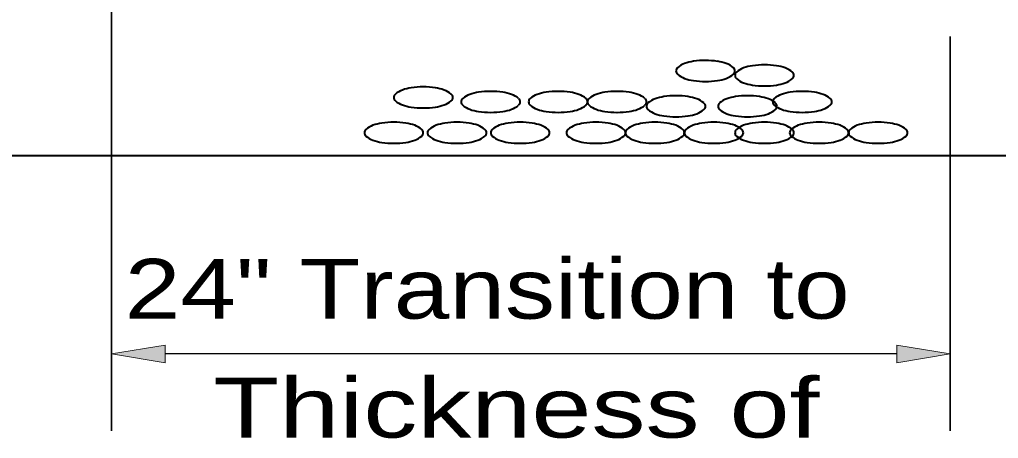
# Model space of a CAD drawing. Extents: x 36.4 to 71.7, y 0.5 to 22.5.
# Drawn here: x 55.644 to 57.934, y 7.945 to 8.925 of the extents above; entities that cross this region are included whole.
import ezdxf

# ---------------------------------------------------------------- set-up
doc = ezdxf.new("R2010")
doc.units = 0
doc.header["$LTSCALE"] = 0.056
for name, color, linetype, lineweight in [('1', 7, 'Continuous', 40), ('3', 7, 'Continuous', 13), ('6', 7, 'Continuous', 13)]:
    doc.layers.add(name, color=color, linetype=linetype, lineweight=lineweight)

msp = doc.modelspace()

# ---------------------------------------------------------------- hatches: boundary and pattern name
at = {"layer": '1'}
for points in [[(55.984, 8.12142), (55.984, 8.163), (55.859, 8.14225), (55.859, 8.14225)], [(57.696, 8.12142), (57.696, 8.163), (57.821, 8.14225), (57.821, 8.14225)]]:
    msp.add_hatch(color=256, dxfattribs=at).paths.add_polyline_path(points)

# ---------------------------------------------------------------- linework, layer by layer
at = {"layer": '1', "lineweight": 35}
for p, q in [((55.859, 9.051), (55.859, 7.96225)), ((57.821, 8.88583), (57.821, 7.96225))]:
    msp.add_line(p, q, dxfattribs=at)
at = {"layer": '1'}
msp.add_line((53.98842, 8.60725), (58.57958, 8.60725), dxfattribs=at)
at = {"layer": '1', "lineweight": 25}
msp.add_line((57.696, 8.14225), (55.984, 8.14225), dxfattribs=at)
at = {"layer": '1', "lineweight": 13}
for points in [[(55.984, 8.12142), (55.984, 8.163), (55.859, 8.14225), (55.859, 8.14225)], [(57.696, 8.12142), (57.696, 8.163), (57.821, 8.14225), (57.821, 8.14225)]]:
    msp.add_lwpolyline(points, close=True, dxfattribs=at)
at = {"layer": '1'}
for centre, radius, start, end in [((57.21717, 8.77267), 0.05258, 109.55636, 130.6711), ((57.23617, 8.72025), 0.10836, 98.47139, 109.71022), ((57.24842, 8.637), 0.19248, 90.02264, 98.43766), ((57.24833, 8.63642), 0.19304, 81.57477, 89.98979), ((57.26058, 8.72067), 0.10795, 70.23479, 81.47362), ((57.2795, 8.77267), 0.05258, 49.32889, 70.44364), ((57.38633, 8.62667), 0.19248, 90.02264, 98.43766), ((57.38625, 8.62608), 0.19304, 81.57477, 89.98979), ((57.18958, 8.80492), 0.01021, 131.07972, 180.31117), ((57.1895, 8.80483), 0.01012, 179.922, 229.15345), ((57.21742, 8.837), 0.05269, 229.11499, 250.22974), ((57.27925, 8.837), 0.05269, 289.77026, 310.885), ((57.30708, 8.80483), 0.01025, 0.19847, 49.42992), ((57.30717, 8.80492), 0.01016, 310.3333, 359.56474), ((57.3275, 8.79458), 0.01021, 131.07972, 180.31117), ((57.32742, 8.7945), 0.01012, 179.922, 229.15345), ((57.35508, 8.76233), 0.05258, 109.55636, 130.6711), ((57.37408, 8.70992), 0.10836, 98.47139, 109.71022), ((57.3985, 8.70992), 0.10836, 70.28977, 81.5286), ((57.4175, 8.76233), 0.05258, 49.32889, 70.44364), ((57.44508, 8.79458), 0.01021, 359.68883, 48.92027), ((57.44517, 8.7945), 0.01012, 310.84655, 0.07799), ((57.23617, 8.88942), 0.10836, 250.28977, 261.5286), ((57.24783, 8.97267), 0.19243, 261.73096, 270.14599), ((57.24883, 8.97325), 0.193, 269.84207, 278.25709), ((57.26058, 8.889), 0.10795, 278.52638, 289.76521), ((57.35533, 8.82667), 0.05269, 229.11499, 250.22974), ((57.37408, 8.87908), 0.10836, 250.28977, 261.5286), ((57.38575, 8.96233), 0.19243, 261.73096, 270.14599), ((57.38675, 8.96292), 0.193, 269.84207, 278.25709), ((57.3985, 8.87908), 0.10836, 278.47139, 289.71023), ((57.41725, 8.82667), 0.05269, 289.77026, 310.885), ((56.52942, 8.74275), 0.01016, 130.3333, 179.56474), ((56.55733, 8.71067), 0.05269, 109.77026, 130.885), ((56.576, 8.65867), 0.10795, 98.52638, 109.76521), ((56.58825, 8.57442), 0.19304, 90.0102, 98.42523), ((56.58817, 8.575), 0.19248, 81.56233, 89.97736), ((56.60042, 8.65825), 0.10836, 70.28977, 81.5286), ((56.61917, 8.71067), 0.05269, 49.11499, 70.22974), ((56.64708, 8.74275), 0.01016, 0.43525, 49.6667), ((56.71492, 8.70033), 0.05269, 109.77026, 130.885), ((56.73367, 8.64792), 0.10836, 98.47139, 109.71022), ((56.74542, 8.56408), 0.193, 89.84207, 98.25709), ((56.74642, 8.56467), 0.19243, 81.73096, 90.14599), ((56.75808, 8.64792), 0.10836, 70.28977, 81.5286), ((56.77683, 8.70033), 0.05269, 49.11499, 70.22974), ((56.87258, 8.70033), 0.05269, 109.77026, 130.885), ((56.89133, 8.64792), 0.10836, 98.47139, 109.71022), ((56.903, 8.56467), 0.19243, 89.85401, 98.26903), ((56.904, 8.56408), 0.193, 81.7429, 90.15793), ((56.91575, 8.64833), 0.10795, 70.23479, 81.47362), ((56.93442, 8.70033), 0.05269, 49.11499, 70.22974), ((57.0105, 8.70033), 0.05269, 109.77026, 130.885), ((57.02925, 8.64792), 0.10836, 98.47139, 109.71022), ((57.04092, 8.56467), 0.19243, 89.85401, 98.26903), ((57.04192, 8.56408), 0.193, 81.7429, 90.15793), ((57.05367, 8.64792), 0.10836, 70.28977, 81.5286), ((57.07242, 8.70033), 0.05269, 49.11499, 70.22974), ((57.444, 8.70033), 0.05269, 109.77026, 130.885), ((57.46275, 8.64792), 0.10836, 98.47139, 109.71022), ((57.4745, 8.56408), 0.193, 89.84207, 98.25709), ((57.4755, 8.56467), 0.19243, 81.73096, 90.14599), ((57.48717, 8.64792), 0.10836, 70.28977, 81.5286), ((57.50592, 8.70033), 0.05269, 49.11499, 70.22974), ((56.5295, 8.74283), 0.01025, 180.19847, 229.42992), ((56.55708, 8.775), 0.05258, 229.32889, 250.44364), ((56.61942, 8.775), 0.05258, 289.55636, 310.6711), ((56.647, 8.74283), 0.01025, 310.57008, 359.80152), ((56.68708, 8.73242), 0.01021, 179.68883, 228.92027), ((56.687, 8.7325), 0.01012, 130.84655, 180.07799), ((56.80475, 8.7325), 0.01012, 359.922, 49.15345), ((56.80467, 8.73242), 0.01021, 311.07972, 0.31117), ((56.84475, 8.73242), 0.01021, 179.68883, 228.92027), ((56.84467, 8.7325), 0.01012, 130.84655, 180.07799), ((56.96233, 8.73242), 0.01016, 0.43525, 49.6667), ((56.96225, 8.7325), 0.01025, 310.57008, 359.80152), ((56.98258, 8.7325), 0.01012, 130.84655, 180.07799), ((56.98267, 8.73242), 0.01021, 179.68883, 228.92027), ((57.10033, 8.7325), 0.01012, 359.922, 49.15345), ((57.10025, 8.73242), 0.01021, 311.07972, 0.31117), ((57.1205, 8.72217), 0.01012, 130.84655, 180.07799), ((57.14842, 8.69), 0.05269, 109.77026, 130.885), ((57.16717, 8.63758), 0.10836, 98.47139, 109.71022), ((57.17892, 8.55375), 0.193, 89.84207, 98.25709), ((57.17992, 8.55433), 0.19243, 81.73096, 90.14599), ((57.19158, 8.63758), 0.10836, 70.28977, 81.5286), ((57.21033, 8.69), 0.05269, 49.11499, 70.22974), ((57.23825, 8.72217), 0.01012, 359.922, 49.15345), ((57.288, 8.72217), 0.01012, 130.84655, 180.07799), ((57.31592, 8.69), 0.05269, 109.77026, 130.885), ((57.33467, 8.63758), 0.10836, 98.47139, 109.71022), ((57.34642, 8.55375), 0.193, 89.84207, 98.25709), ((57.34742, 8.55433), 0.19243, 81.73096, 90.14599), ((57.35908, 8.63758), 0.10836, 70.28977, 81.5286), ((57.37783, 8.69), 0.05269, 49.11499, 70.22974), ((57.41608, 8.7325), 0.01012, 130.84655, 180.07799), ((57.41617, 8.73242), 0.01021, 179.68883, 228.92027), ((57.40575, 8.72217), 0.01012, 359.922, 49.15345), ((57.53383, 8.7325), 0.01012, 359.922, 49.15345), ((57.53375, 8.73242), 0.01021, 311.07972, 0.31117), ((56.576, 8.827), 0.10795, 250.23479, 261.47362), ((56.58825, 8.91125), 0.19304, 261.57477, 269.98979), ((56.58817, 8.91067), 0.19248, 270.02264, 278.43766), ((56.60042, 8.82742), 0.10836, 278.47139, 289.71023), ((56.71467, 8.76467), 0.05258, 229.32889, 250.44364), ((56.73367, 8.81708), 0.10836, 250.28977, 261.5286), ((56.74592, 8.90092), 0.19304, 261.57477, 269.98979), ((56.74583, 8.90033), 0.19248, 270.02264, 278.43766), ((56.75808, 8.81708), 0.10836, 278.47139, 289.71023), ((56.77708, 8.76467), 0.05258, 289.55636, 310.6711), ((56.87233, 8.76467), 0.05258, 229.32889, 250.44364), ((56.89133, 8.81708), 0.10836, 250.28977, 261.5286), ((56.90358, 8.90033), 0.19248, 261.56233, 269.97736), ((56.9035, 8.90092), 0.19304, 270.0102, 278.42523), ((56.91575, 8.81667), 0.10795, 278.52638, 289.76521), ((56.93467, 8.76467), 0.05258, 289.55636, 310.6711), ((57.01025, 8.76467), 0.05258, 229.32889, 250.44364), ((57.02925, 8.81708), 0.10836, 250.28977, 261.5286), ((57.0415, 8.90033), 0.19248, 261.56233, 269.97736), ((57.04142, 8.90092), 0.19304, 270.0102, 278.42523), ((57.05367, 8.81708), 0.10836, 278.47139, 289.71023), ((57.07267, 8.76467), 0.05258, 289.55636, 310.6711), ((57.12058, 8.72208), 0.01021, 179.68883, 228.92027), ((57.14817, 8.75433), 0.05258, 229.32889, 250.44364), ((57.16717, 8.80675), 0.10836, 250.28977, 261.5286), ((57.19158, 8.80675), 0.10836, 278.47139, 289.71023), ((57.21058, 8.75433), 0.05258, 289.55636, 310.6711), ((57.23817, 8.72208), 0.01021, 311.07972, 0.31117), ((57.28808, 8.72208), 0.01021, 179.68883, 228.92027), ((57.31567, 8.75433), 0.05258, 229.32889, 250.44364), ((57.33467, 8.80675), 0.10836, 250.28977, 261.5286), ((57.35908, 8.80675), 0.10836, 278.47139, 289.71023), ((57.37808, 8.75433), 0.05258, 289.55636, 310.6711), ((57.44375, 8.76467), 0.05258, 229.32889, 250.44364), ((57.40567, 8.72208), 0.01021, 311.07972, 0.31117), ((57.46275, 8.81708), 0.10836, 250.28977, 261.5286), ((57.475, 8.90092), 0.19304, 261.57477, 269.98979), ((57.47492, 8.90033), 0.19248, 270.02264, 278.43766), ((57.48717, 8.81708), 0.10836, 278.47139, 289.71023), ((57.50617, 8.76467), 0.05258, 289.55636, 310.6711), ((56.50658, 8.5755), 0.10826, 98.25297, 109.4918), ((56.51933, 8.49225), 0.19248, 90.02264, 98.43766), ((56.51925, 8.49167), 0.19304, 81.57477, 89.98979), ((56.532, 8.5755), 0.10826, 70.5082, 81.74703), ((56.65442, 8.57592), 0.10785, 98.30717, 109.546), ((56.66708, 8.49167), 0.19304, 90.0102, 98.42523), ((56.667, 8.49225), 0.19248, 81.56233, 89.97736), ((56.67975, 8.5755), 0.10826, 70.5082, 81.74703), ((56.80217, 8.5755), 0.10826, 98.25297, 109.4918), ((56.81492, 8.49225), 0.19248, 90.02264, 98.43766), ((56.81483, 8.49167), 0.19304, 81.57477, 89.98979), ((56.8275, 8.57592), 0.10785, 70.454, 81.69283), ((56.9795, 8.5755), 0.10826, 98.25297, 109.4918), ((56.99225, 8.49225), 0.19248, 90.02264, 98.43766), ((56.99217, 8.49167), 0.19304, 81.57477, 89.98979), ((57.00492, 8.5755), 0.10826, 70.5082, 81.74703), ((57.11742, 8.5755), 0.10826, 98.25297, 109.4918), ((57.13017, 8.49167), 0.19304, 90.0102, 98.42523), ((57.13008, 8.49225), 0.19248, 81.56233, 89.97736), ((57.17942, 8.89058), 0.19304, 261.57477, 269.98979), ((57.14283, 8.5755), 0.10826, 70.5082, 81.74703), ((57.17933, 8.89), 0.19248, 270.02264, 278.43766), ((57.25542, 8.57592), 0.10785, 98.30717, 109.546), ((57.26808, 8.49167), 0.19304, 90.0102, 98.42523), ((57.268, 8.49225), 0.19248, 81.56233, 89.97736), ((57.28075, 8.5755), 0.10826, 70.5082, 81.74703), ((57.34692, 8.89058), 0.19304, 261.57477, 269.98979), ((57.37358, 8.5755), 0.10826, 98.25297, 109.4918), ((57.34683, 8.89), 0.19248, 270.02264, 278.43766), ((57.38633, 8.49225), 0.19248, 90.02264, 98.43766), ((57.38625, 8.49167), 0.19304, 81.57477, 89.98979), ((57.399, 8.5755), 0.10826, 70.5082, 81.74703), ((57.50167, 8.5755), 0.10826, 98.25297, 109.4918), ((57.51442, 8.49225), 0.19248, 90.02264, 98.43766), ((57.51433, 8.49167), 0.19304, 81.57477, 89.98979), ((57.52708, 8.5755), 0.10826, 70.5082, 81.74703), ((57.63958, 8.5755), 0.10826, 98.25297, 109.4918), ((57.65233, 8.49167), 0.19304, 90.0102, 98.42523), ((57.65225, 8.49225), 0.19248, 81.56233, 89.97736), ((57.665, 8.5755), 0.10826, 70.5082, 81.74703), ((56.4605, 8.66008), 0.01021, 179.68883, 228.92027), ((56.46042, 8.66017), 0.01012, 130.84655, 180.07799), ((56.48833, 8.628), 0.05269, 109.77026, 130.885), ((56.55025, 8.628), 0.05269, 49.11499, 70.22974), ((56.57817, 8.66017), 0.01012, 359.922, 49.15345), ((56.57808, 8.66008), 0.01021, 311.07972, 0.31117), ((56.60833, 8.66017), 0.01025, 180.19847, 229.42992), ((56.60825, 8.66008), 0.01016, 130.3333, 179.56474), ((56.63617, 8.628), 0.05269, 109.77026, 130.885), ((56.698, 8.628), 0.05269, 49.11499, 70.22974), ((56.72592, 8.66017), 0.01012, 359.922, 49.15345), ((56.72583, 8.66008), 0.01021, 311.07972, 0.31117), ((56.75608, 8.66008), 0.01021, 179.68883, 228.92027), ((56.756, 8.66017), 0.01012, 130.84655, 180.07799), ((56.78392, 8.628), 0.05269, 109.77026, 130.885), ((56.84575, 8.628), 0.05269, 49.11499, 70.22974), ((56.87367, 8.66008), 0.01016, 0.43525, 49.6667), ((56.87358, 8.66017), 0.01025, 310.57008, 359.80152), ((56.93333, 8.66017), 0.01012, 130.84655, 180.07799), ((56.93342, 8.66008), 0.01021, 179.68883, 228.92027), ((56.96125, 8.628), 0.05269, 109.77026, 130.885), ((57.02317, 8.628), 0.05269, 49.11499, 70.22974), ((57.05108, 8.66017), 0.01012, 359.922, 49.15345), ((57.051, 8.66008), 0.01021, 311.07972, 0.31117), ((57.07133, 8.66008), 0.01021, 179.68883, 228.92027), ((57.07125, 8.66017), 0.01012, 130.84655, 180.07799), ((57.09917, 8.628), 0.05269, 109.77026, 130.885), ((57.16108, 8.628), 0.05269, 49.11499, 70.22974), ((57.189, 8.66017), 0.01012, 359.922, 49.15345), ((57.18892, 8.66008), 0.01021, 311.07972, 0.31117), ((57.20933, 8.66017), 0.01025, 180.19847, 229.42992), ((57.20925, 8.66008), 0.01016, 130.3333, 179.56474), ((57.23717, 8.628), 0.05269, 109.77026, 130.885), ((57.299, 8.628), 0.05269, 49.11499, 70.22974), ((57.3275, 8.66008), 0.01021, 179.68883, 228.92027), ((57.32742, 8.66017), 0.01012, 130.84655, 180.07799), ((57.35533, 8.628), 0.05269, 109.77026, 130.885), ((57.32692, 8.66017), 0.01012, 359.922, 49.15345), ((57.32683, 8.66008), 0.01021, 311.07972, 0.31117), ((57.41725, 8.628), 0.05269, 49.11499, 70.22974), ((57.45558, 8.66008), 0.01021, 179.68883, 228.92027), ((57.4555, 8.66017), 0.01012, 130.84655, 180.07799), ((57.48342, 8.628), 0.05269, 109.77026, 130.885), ((57.44517, 8.66017), 0.01012, 359.922, 49.15345), ((57.44508, 8.66008), 0.01021, 311.07972, 0.31117), ((57.54533, 8.628), 0.05269, 49.11499, 70.22974), ((57.57325, 8.66017), 0.01012, 359.922, 49.15345), ((57.57317, 8.66008), 0.01021, 311.07972, 0.31117), ((57.5935, 8.66008), 0.01021, 179.68883, 228.92027), ((57.59342, 8.66017), 0.01012, 130.84655, 180.07799), ((57.62133, 8.628), 0.05269, 109.77026, 130.885), ((57.68325, 8.628), 0.05269, 49.11499, 70.22974), ((57.71117, 8.66017), 0.01012, 359.922, 49.15345), ((57.71108, 8.66008), 0.01021, 311.07972, 0.31117), ((56.48808, 8.69233), 0.05258, 229.32889, 250.44364), ((56.50708, 8.74475), 0.10836, 250.28977, 261.5286), ((56.51933, 8.828), 0.19248, 261.56233, 269.97736), ((56.51925, 8.82858), 0.19304, 270.0102, 278.42523), ((56.5315, 8.74475), 0.10836, 278.47139, 289.71023), ((56.5505, 8.69233), 0.05258, 289.55636, 310.6711), ((56.63592, 8.69233), 0.05258, 229.32889, 250.44364), ((56.65483, 8.74433), 0.10795, 250.23479, 261.47362), ((56.66708, 8.82858), 0.19304, 261.57477, 269.98979), ((56.667, 8.828), 0.19248, 270.02264, 278.43766), ((56.67925, 8.74475), 0.10836, 278.47139, 289.71023), ((56.69825, 8.69233), 0.05258, 289.55636, 310.6711), ((56.78367, 8.69233), 0.05258, 229.32889, 250.44364), ((56.80267, 8.74475), 0.10836, 250.28977, 261.5286), ((56.81492, 8.828), 0.19248, 261.56233, 269.97736), ((56.81483, 8.82858), 0.19304, 270.0102, 278.42523), ((56.82708, 8.74433), 0.10795, 278.52638, 289.76521), ((56.846, 8.69233), 0.05258, 289.55636, 310.6711), ((56.961, 8.69233), 0.05258, 229.32889, 250.44364), ((56.98, 8.74475), 0.10836, 250.28977, 261.5286), ((56.99225, 8.828), 0.19248, 261.56233, 269.97736), ((56.99217, 8.82858), 0.19304, 270.0102, 278.42523), ((57.00442, 8.74475), 0.10836, 278.47139, 289.71023), ((57.02342, 8.69233), 0.05258, 289.55636, 310.6711), ((57.09892, 8.69233), 0.05258, 229.32889, 250.44364), ((57.11792, 8.74475), 0.10836, 250.28977, 261.5286), ((57.13017, 8.82858), 0.19304, 261.57477, 269.98979), ((57.13008, 8.828), 0.19248, 270.02264, 278.43766), ((57.14233, 8.74475), 0.10836, 278.47139, 289.71023), ((57.16133, 8.69233), 0.05258, 289.55636, 310.6711), ((57.23692, 8.69233), 0.05258, 229.32889, 250.44364), ((57.25583, 8.74433), 0.10795, 250.23479, 261.47362), ((57.26808, 8.82858), 0.19304, 261.57477, 269.98979), ((57.268, 8.828), 0.19248, 270.02264, 278.43766), ((57.28025, 8.74475), 0.10836, 278.47139, 289.71023), ((57.29925, 8.69233), 0.05258, 289.55636, 310.6711), ((57.35508, 8.69233), 0.05258, 229.32889, 250.44364), ((57.37408, 8.74475), 0.10836, 250.28977, 261.5286), ((57.38633, 8.828), 0.19248, 261.56233, 269.97736), ((57.38625, 8.82858), 0.19304, 270.0102, 278.42523), ((57.3985, 8.74475), 0.10836, 278.47139, 289.71023), ((57.4175, 8.69233), 0.05258, 289.55636, 310.6711), ((57.48317, 8.69233), 0.05258, 229.32889, 250.44364), ((57.50217, 8.74475), 0.10836, 250.28977, 261.5286), ((57.51442, 8.828), 0.19248, 261.56233, 269.97736), ((57.51433, 8.82858), 0.19304, 270.0102, 278.42523), ((57.52658, 8.74475), 0.10836, 278.47139, 289.71023), ((57.54558, 8.69233), 0.05258, 289.55636, 310.6711), ((57.62108, 8.69233), 0.05258, 229.32889, 250.44364), ((57.64008, 8.74475), 0.10836, 250.28977, 261.5286), ((57.65233, 8.82858), 0.19304, 261.57477, 269.98979), ((57.65225, 8.828), 0.19248, 270.02264, 278.43766), ((57.6645, 8.74475), 0.10836, 278.47139, 289.71023), ((57.6835, 8.69233), 0.05258, 289.55636, 310.6711)]:
    msp.add_arc(centre, radius, start, end, dxfattribs=at)
at = {"layer": '6'}
msp.add_line((55.859, 8.14225), (55.85908, 8.14225), dxfattribs=at)

# ---------------------------------------------------------------- texts
at = {"layer": '3'}
for s, width, p in [('24" Transition to', 1.25, (55.88983, 8.22492)), ('Thickness of', 1.35, (56.09675, 7.9465))]:
    msp.add_text(s, height=0.14, dxfattribs=dict(at, width=width)).set_placement(p)

doc.saveas('drawing.dxf')
